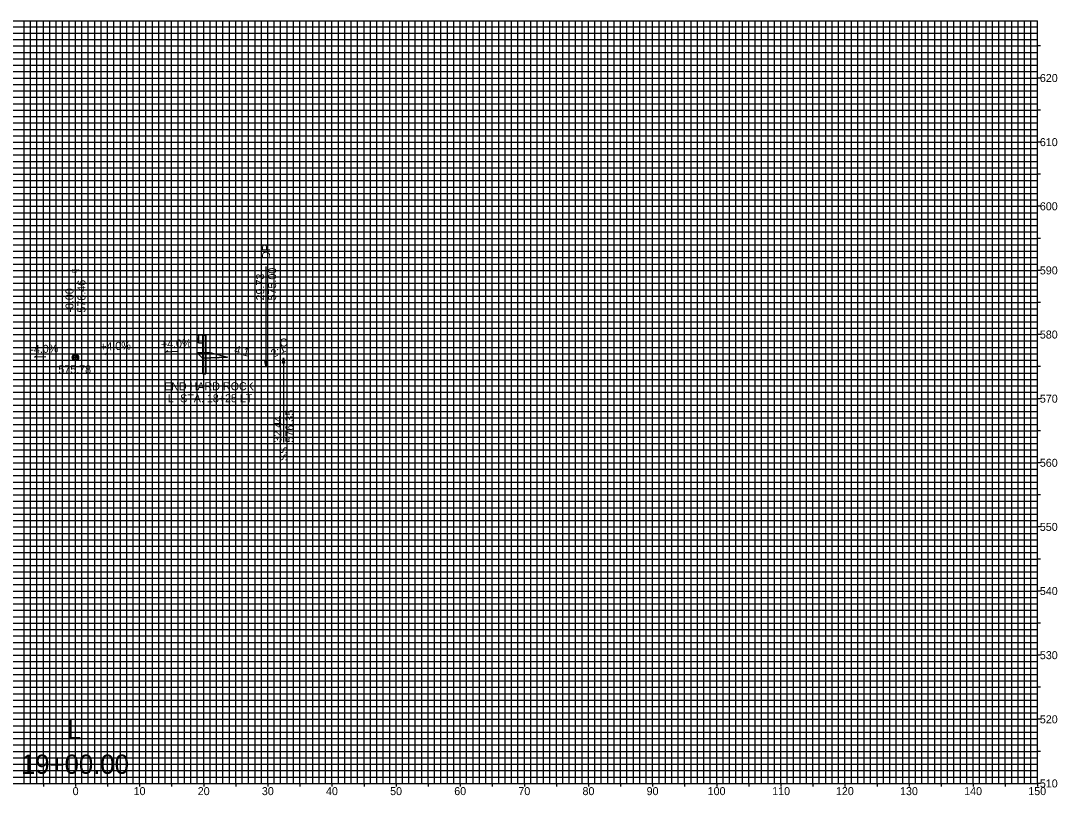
# Model space of a CAD drawing. Extents: x -153 to 153, y 508 to 629.
# Drawn here: x -8.5 to 153.1, y 508.2 to 628.9 of the extents above; entities that cross this region are included whole.
import ezdxf

# ---------------------------------------------------------------- set-up
doc = ezdxf.new("R2010")
doc.units = 0
for name, color, linetype in [('_CIVIL_CONSTRUCTION', 7, 'Continuous'), ('E_NCDOT_XS_Center_Line_Elevation_Label', 7, 'Continuous'), ('Level_63', 7, 'Continuous'), ('P_NCDOT_XS_Label_Grade_Point', 7, 'Continuous'), ('P_NCDOT_XS_Label_Grading_Side_Slope', 7, 'Continuous'), ('P_NCDOT_XS_Label_Slope_Minor', 7, 'Continuous'), ('P_NCDOT_XS_Label_Slope_Superelevation', 7, 'Continuous'), ('P_NCDOT_XS_Leader_Line', 7, 'Continuous'), ('P_NCDOT_XS_Sheet_Alignment_Station_Label', 7, 'Continuous'), ('P_NCDOT_XS_Sheet_Annotation_Label', 7, 'Continuous'), ('P_NCDOT_XS_Sheet_Grid_Border', 7, 'Continuous'), ('Prop XS Grade Point', 7, 'Continuous'), ('Prop XS Label Slope Superelevation', 7, 'Continuous'), ('Scratch_Level_3', 7, 'Continuous'), ('Scratch_Level_4', 7, 'Continuous'), ('Sheet_Grid_Major', 7, 'Continuous'), ('Sheet_Grid_Middle', 7, 'Continuous'), ('Sheet_Grid_Minor', 7, 'Continuous')]:
    doc.layers.add(name, color=color, linetype=linetype)

msp = doc.modelspace()

# ---------------------------------------------------------------- linework, layer by layer
at = {"layer": '_CIVIL_CONSTRUCTION'}
for p, q in [((19.08, 579.79), (18.94, 579.69)), ((18.94, 579.56), (19.15, 579.42)), ((19.15, 579.19), (18.94, 579.05)), ((18.94, 578.92), (19.08, 578.82)), ((19.18, 579.81), (19.09, 579.79)), ((19.09, 578.82), (19.18, 578.8)), ((19.85, 579.89), (19.19, 579.89)), ((19.19, 579.89), (19.19, 578.72)), ((19.19, 579.35), (19.19, 579.3)), ((19.19, 579.3), (19.19, 579.26)), ((19.19, 578.72), (19.85, 578.72)), ((19.85, 579.89), (20.35, 579.89)), ((19.87, 579.89), (19.85, 579.89)), ((19.85, 579.89), (19.85, 573.89)), ((19.87, 573.89), (19.87, 579.89)), ((20.35, 579.89), (20.34, 579.89)), ((20.34, 579.89), (20.34, 573.89)), ((20.35, 573.89), (20.35, 579.89)), ((19.85, 573.89), (20.35, 573.89)), ((19.85, 573.89), (19.87, 573.89)), ((20.34, 573.89), (20.35, 573.89))]:
    msp.add_line(p, q, dxfattribs=at)
for centre, radius, start, end in [((18.99, 579.63), 0.0787, 125.2976, 235.3478), ((18.99, 578.98), 0.0787, 124.6522, 234.7024), ((19.1, 579.76), 0.0328, 100, 125.2976), ((19.1, 578.85), 0.0328, 234.7024, 260), ((19.11, 579.35), 0.0787, 0.02, 55.3478), ((19.11, 579.26), 0.0787, 304.6522, 359.98)]:
    msp.add_arc(centre, radius, start, end, dxfattribs=at)
at = {"layer": 'E_NCDOT_XS_Center_Line_Elevation_Label'}
for p, q in [((4.6, 576.89), (4.93, 577.14)), ((14.06, 577.27), (14.39, 577.52)), ((15.85, 577.34), (14.06, 577.27)), ((-6.4, 576.45), (-6.07, 576.7)), ((-4.6, 576.52), (-6.4, 576.45)), ((6.4, 576.96), (4.6, 576.89))]:
    msp.add_line(p, q, dxfattribs=at)
at = {"layer": 'Level_63'}
msp.add_line((11, 576.9), (11, 577.53), dxfattribs=at)
at = {"layer": 'P_NCDOT_XS_Label_Grade_Point'}
for p, q in [((29.73, 575), (29.73, 590.6)), ((0, 576.46), (0, 588.94)), ((32.44, 576.35), (32.44, 563.15)), ((32.44, 576.35), (32.44, 563.15))]:
    msp.add_line(p, q, dxfattribs=at)
for points in [[(0.3, 576.16), (-0.3, 576.16), (-0.3, 576.76), (0.3, 576.76)], [(29.73, 575), (29.55, 575.82), (29.9, 575.82)], [(32.44, 576.35), (32.62, 575.53), (32.27, 575.53)], [(32.44, 576.35), (32.62, 575.53), (32.27, 575.53)]]:
    msp.add_lwpolyline(points, close=True, dxfattribs=at)
at = {"layer": 'P_NCDOT_XS_Sheet_Grid_Border'}
for p, q in [((-150, 628.94), (150, 628.94)), ((150, 510), (150, 628.94)), ((-150, 510), (150, 510))]:
    msp.add_line(p, q, dxfattribs=at)
at = {"layer": 'Prop XS Label Slope Superelevation'}
for p, q in [((-0.5, 576.46), (0.5, 576.46)), ((0, 576.96), (0, 575.96))]:
    msp.add_line(p, q, dxfattribs=at)
for points in [[(-0.5, 576.46), (0, 576.46), (0, 576.96)], [(0.5, 576.46), (0, 576.46), (0, 575.96)]]:
    msp.add_lwpolyline(points, dxfattribs=at)
msp.add_circle((0, 576.46), 0.5, dxfattribs=at)
for start, end in [(90, 180), (270, 0)]:
    msp.add_arc((0, 576.46), 0.5, start, end, dxfattribs=at)
at = {"layer": 'Scratch_Level_3'}
msp.add_line((19.79, 576.34), (23.73, 576.5), dxfattribs=at)
at = {"layer": 'Scratch_Level_4'}
msp.add_lwpolyline([(18.91, 577.22), (21, 577.18), (23.73, 576.5), (19.79, 576.34)], close=True, dxfattribs=at)
at = {"layer": 'Sheet_Grid_Major'}
for p, q in [((0, 510), (0, 628.94)), ((10, 510), (10, 628.94)), ((20, 510), (20, 628.94)), ((30, 510), (30, 628.94)), ((40, 510), (40, 628.94)), ((50, 510), (50, 628.94)), ((60, 510), (60, 628.94)), ((70, 510), (70, 628.94)), ((80, 510), (80, 628.94)), ((90, 510), (90, 628.94)), ((100, 510), (100, 628.94)), ((110, 510), (110, 628.94)), ((120, 510), (120, 628.94)), ((130, 510), (130, 628.94)), ((140, 510), (140, 628.94)), ((-150, 620), (150, 620)), ((-150, 610), (150, 610)), ((-150, 600), (150, 600)), ((-150, 590), (150, 590)), ((-150, 580), (150, 580)), ((-150, 570), (150, 570)), ((-150, 560), (150, 560)), ((-150, 550), (150, 550)), ((-150, 540), (150, 540)), ((-150, 530), (150, 530)), ((-150, 520), (150, 520))]:
    msp.add_line(p, q, dxfattribs=at)
at = {"layer": 'Sheet_Grid_Middle'}
for p, q in [((-5, 510), (-5, 628.94)), ((0, 510), (0, 628.94)), ((5, 510), (5, 628.94)), ((10, 510), (10, 628.94)), ((15, 510), (15, 628.94)), ((20, 510), (20, 628.94)), ((25, 510), (25, 628.94)), ((30, 510), (30, 628.94)), ((35, 510), (35, 628.94)), ((40, 510), (40, 628.94)), ((45, 510), (45, 628.94)), ((50, 510), (50, 628.94)), ((55, 510), (55, 628.94)), ((60, 510), (60, 628.94)), ((65, 510), (65, 628.94)), ((70, 510), (70, 628.94)), ((75, 510), (75, 628.94)), ((80, 510), (80, 628.94)), ((85, 510), (85, 628.94)), ((90, 510), (90, 628.94)), ((95, 510), (95, 628.94)), ((100, 510), (100, 628.94)), ((105, 510), (105, 628.94)), ((110, 510), (110, 628.94)), ((115, 510), (115, 628.94)), ((120, 510), (120, 628.94)), ((125, 510), (125, 628.94)), ((130, 510), (130, 628.94)), ((135, 510), (135, 628.94)), ((140, 510), (140, 628.94)), ((145, 510), (145, 628.94)), ((-150, 625), (150, 625)), ((150.48, 625), (150, 625)), ((-150, 620), (150, 620)), ((150.48, 620), (150, 620)), ((-150, 615), (150, 615)), ((150.48, 615), (150, 615)), ((-150, 610), (150, 610)), ((150.48, 610), (150, 610)), ((-150, 605), (150, 605)), ((150.48, 605), (150, 605)), ((-150, 600), (150, 600)), ((150.48, 600), (150, 600)), ((-150, 595), (150, 595)), ((150.48, 595), (150, 595)), ((-150, 590), (150, 590)), ((150.48, 590), (150, 590)), ((-150, 585), (150, 585)), ((150.48, 585), (150, 585)), ((-150, 580), (150, 580)), ((150.48, 580), (150, 580)), ((-150, 575), (150, 575)), ((150.48, 575), (150, 575)), ((-150, 570), (150, 570)), ((150.48, 570), (150, 570)), ((-150, 565), (150, 565)), ((150.48, 565), (150, 565)), ((-150, 560), (150, 560)), ((150.48, 560), (150, 560)), ((-150, 555), (150, 555)), ((150.48, 555), (150, 555)), ((-150, 550), (150, 550)), ((150.48, 550), (150, 550)), ((-150, 545), (150, 545)), ((150.48, 545), (150, 545)), ((-150, 540), (150, 540)), ((150.48, 540), (150, 540)), ((-150, 535), (150, 535)), ((150.48, 535), (150, 535)), ((-150, 530), (150, 530)), ((150.48, 530), (150, 530)), ((-150, 525), (150, 525)), ((150.48, 525), (150, 525)), ((-150, 520), (150, 520)), ((150.48, 520), (150, 520)), ((-150, 515), (150, 515)), ((150.48, 515), (150, 515)), ((-5, 510), (-5, 509.52)), ((0, 510), (0, 509.52)), ((5, 510), (5, 509.52)), ((10, 510), (10, 509.52)), ((15, 510), (15, 509.52)), ((20, 510), (20, 509.52)), ((25, 510), (25, 509.52)), ((30, 510), (30, 509.52)), ((35, 510), (35, 509.52)), ((40, 510), (40, 509.52)), ((45, 510), (45, 509.52)), ((50, 510), (50, 509.52)), ((55, 510), (55, 509.52)), ((60, 510), (60, 509.52)), ((65, 510), (65, 509.52)), ((70, 510), (70, 509.52)), ((75, 510), (75, 509.52)), ((80, 510), (80, 509.52)), ((85, 510), (85, 509.52)), ((90, 510), (90, 509.52)), ((95, 510), (95, 509.52)), ((100, 510), (100, 509.52)), ((105, 510), (105, 509.52)), ((110, 510), (110, 509.52)), ((115, 510), (115, 509.52)), ((120, 510), (120, 509.52)), ((125, 510), (125, 509.52)), ((130, 510), (130, 509.52)), ((135, 510), (135, 509.52)), ((140, 510), (140, 509.52)), ((145, 510), (145, 509.52)), ((150, 510), (150, 509.52)), ((150.48, 510), (150, 510))]:
    msp.add_line(p, q, dxfattribs=at)
at = {"layer": 'Sheet_Grid_Minor'}
for p, q in [((-8, 510), (-8, 628.94)), ((-7, 510), (-7, 628.94)), ((-6, 510), (-6, 628.94)), ((-4, 510), (-4, 628.94)), ((-3, 510), (-3, 628.94)), ((-2, 510), (-2, 628.94)), ((-1, 510), (-1, 628.94)), ((1, 510), (1, 628.94)), ((2, 510), (2, 628.94)), ((3, 510), (3, 628.94)), ((4, 510), (4, 628.94)), ((6, 510), (6, 628.94)), ((7, 510), (7, 628.94)), ((8, 510), (8, 628.94)), ((9, 510), (9, 628.94)), ((11, 510), (11, 628.94)), ((12, 510), (12, 628.94)), ((13, 510), (13, 628.94)), ((14, 510), (14, 628.94)), ((16, 510), (16, 628.94)), ((17, 510), (17, 628.94)), ((18, 510), (18, 628.94)), ((19, 510), (19, 628.94)), ((21, 510), (21, 628.94)), ((22, 510), (22, 628.94)), ((23, 510), (23, 628.94)), ((24, 510), (24, 628.94)), ((26, 510), (26, 628.94)), ((27, 510), (27, 628.94)), ((28, 510), (28, 628.94)), ((29, 510), (29, 628.94)), ((31, 510), (31, 628.94)), ((32, 510), (32, 628.94)), ((33, 510), (33, 628.94)), ((34, 510), (34, 628.94)), ((36, 510), (36, 628.94)), ((37, 510), (37, 628.94)), ((38, 510), (38, 628.94)), ((39, 510), (39, 628.94)), ((41, 510), (41, 628.94)), ((42, 510), (42, 628.94)), ((43, 510), (43, 628.94)), ((44, 510), (44, 628.94)), ((46, 510), (46, 628.94)), ((47, 510), (47, 628.94)), ((48, 510), (48, 628.94)), ((49, 510), (49, 628.94)), ((51, 510), (51, 628.94)), ((52, 510), (52, 628.94)), ((53, 510), (53, 628.94)), ((54, 510), (54, 628.94)), ((56, 510), (56, 628.94)), ((57, 510), (57, 628.94)), ((58, 510), (58, 628.94)), ((59, 510), (59, 628.94)), ((61, 510), (61, 628.94)), ((62, 510), (62, 628.94)), ((63, 510), (63, 628.94)), ((64, 510), (64, 628.94)), ((66, 510), (66, 628.94)), ((67, 510), (67, 628.94)), ((68, 510), (68, 628.94)), ((69, 510), (69, 628.94)), ((71, 510), (71, 628.94)), ((72, 510), (72, 628.94)), ((73, 510), (73, 628.94)), ((74, 510), (74, 628.94)), ((76, 510), (76, 628.94)), ((77, 510), (77, 628.94)), ((78, 510), (78, 628.94)), ((79, 510), (79, 628.94)), ((81, 510), (81, 628.94)), ((82, 510), (82, 628.94)), ((83, 510), (83, 628.94)), ((84, 510), (84, 628.94)), ((86, 510), (86, 628.94)), ((87, 510), (87, 628.94)), ((88, 510), (88, 628.94)), ((89, 510), (89, 628.94)), ((91, 510), (91, 628.94)), ((92, 510), (92, 628.94)), ((93, 510), (93, 628.94)), ((94, 510), (94, 628.94)), ((96, 510), (96, 628.94)), ((97, 510), (97, 628.94)), ((98, 510), (98, 628.94)), ((99, 510), (99, 628.94)), ((101, 510), (101, 628.94)), ((102, 510), (102, 628.94)), ((103, 510), (103, 628.94)), ((104, 510), (104, 628.94)), ((106, 510), (106, 628.94)), ((107, 510), (107, 628.94)), ((108, 510), (108, 628.94)), ((109, 510), (109, 628.94)), ((111, 510), (111, 628.94)), ((112, 510), (112, 628.94)), ((113, 510), (113, 628.94)), ((114, 510), (114, 628.94)), ((116, 510), (116, 628.94)), ((117, 510), (117, 628.94)), ((118, 510), (118, 628.94)), ((119, 510), (119, 628.94)), ((121, 510), (121, 628.94)), ((122, 510), (122, 628.94)), ((123, 510), (123, 628.94)), ((124, 510), (124, 628.94)), ((126, 510), (126, 628.94)), ((127, 510), (127, 628.94)), ((128, 510), (128, 628.94)), ((129, 510), (129, 628.94)), ((131, 510), (131, 628.94)), ((132, 510), (132, 628.94)), ((133, 510), (133, 628.94)), ((134, 510), (134, 628.94)), ((136, 510), (136, 628.94)), ((137, 510), (137, 628.94)), ((138, 510), (138, 628.94)), ((139, 510), (139, 628.94)), ((141, 510), (141, 628.94)), ((142, 510), (142, 628.94)), ((143, 510), (143, 628.94)), ((144, 510), (144, 628.94)), ((146, 510), (146, 628.94)), ((147, 510), (147, 628.94)), ((148, 510), (148, 628.94)), ((149, 510), (149, 628.94)), ((-150, 628), (150, 628)), ((-150, 627), (150, 627)), ((-150, 626), (150, 626)), ((-150, 624), (150, 624)), ((-150, 623), (150, 623)), ((-150, 622), (150, 622)), ((-150, 621), (150, 621)), ((-150, 619), (150, 619)), ((-150, 618), (150, 618)), ((-150, 617), (150, 617)), ((-150, 616), (150, 616)), ((-150, 614), (150, 614)), ((-150, 613), (150, 613)), ((-150, 612), (150, 612)), ((-150, 611), (150, 611)), ((-150, 609), (150, 609)), ((-150, 608), (150, 608)), ((-150, 607), (150, 607)), ((-150, 606), (150, 606)), ((-150, 604), (150, 604)), ((-150, 603), (150, 603)), ((-150, 602), (150, 602)), ((-150, 601), (150, 601)), ((-150, 599), (150, 599)), ((-150, 598), (150, 598)), ((-150, 597), (150, 597)), ((-150, 596), (150, 596)), ((-150, 594), (150, 594)), ((-150, 593), (150, 593)), ((-150, 592), (150, 592)), ((-150, 591), (150, 591)), ((-150, 589), (150, 589)), ((-150, 588), (150, 588)), ((-150, 587), (150, 587)), ((-150, 586), (150, 586)), ((-150, 584), (150, 584)), ((-150, 583), (150, 583)), ((-150, 582), (150, 582)), ((-150, 581), (150, 581)), ((-150, 579), (150, 579)), ((-150, 578), (150, 578)), ((-150, 577), (150, 577)), ((-150, 576), (150, 576)), ((-150, 574), (150, 574)), ((-150, 573), (150, 573)), ((-150, 572), (150, 572)), ((-150, 571), (150, 571)), ((-150, 569), (150, 569)), ((-150, 568), (150, 568)), ((-150, 567), (150, 567)), ((-150, 566), (150, 566)), ((-150, 564), (150, 564)), ((-150, 563), (150, 563)), ((-150, 562), (150, 562)), ((-150, 561), (150, 561)), ((-150, 559), (150, 559)), ((-150, 558), (150, 558)), ((-150, 557), (150, 557)), ((-150, 556), (150, 556)), ((-150, 554), (150, 554)), ((-150, 553), (150, 553)), ((-150, 552), (150, 552)), ((-150, 551), (150, 551)), ((-150, 549), (150, 549)), ((-150, 548), (150, 548)), ((-150, 547), (150, 547)), ((-150, 546), (150, 546)), ((-150, 544), (150, 544)), ((-150, 543), (150, 543)), ((-150, 542), (150, 542)), ((-150, 541), (150, 541)), ((-150, 539), (150, 539)), ((-150, 538), (150, 538)), ((-150, 537), (150, 537)), ((-150, 536), (150, 536)), ((-150, 534), (150, 534)), ((-150, 533), (150, 533)), ((-150, 532), (150, 532)), ((-150, 531), (150, 531)), ((-150, 529), (150, 529)), ((-150, 528), (150, 528)), ((-150, 527), (150, 527)), ((-150, 526), (150, 526)), ((-150, 524), (150, 524)), ((-150, 523), (150, 523)), ((-150, 522), (150, 522)), ((-150, 521), (150, 521)), ((-150, 519), (150, 519)), ((-150, 518), (150, 518)), ((-150, 517), (150, 517)), ((-150, 516), (150, 516)), ((-150, 514), (150, 514)), ((-150, 513), (150, 513)), ((-150, 512), (150, 512)), ((-150, 511), (150, 511))]:
    msp.add_line(p, q, dxfattribs=at)

# ---------------------------------------------------------------- texts
at = {"layer": 'P_NCDOT_XS_Label_Grading_Side_Slope'}
msp.add_text('GP', height=0.624, dxfattribs=at).set_placement((-0.61, 589.61))
for s, p in [('576.46', (1.56, 583.42)), ('-0.00', (-0.31, 583.42))]:
    msp.add_text(s, height=1.248, rotation=90, dxfattribs=at).set_placement(p)
at = {"layer": 'P_NCDOT_XS_Label_Slope_Minor'}
msp.add_text('575.78', height=1.248, dxfattribs=at).set_placement((-2.67, 573.95))
at = {"layer": 'P_NCDOT_XS_Label_Slope_Superelevation'}
for s, rotation, p in [('+4.0%', 2.2906, (13.34, 577.87)), ('4:1', 345.9638, (24.67, 577.12)), ('2:1', 26.5651, (30.86, 576.36))]:
    msp.add_text(s, height=1.248, rotation=rotation, dxfattribs=at).set_placement(p)
at = {"layer": 'P_NCDOT_XS_Leader_Line'}
for s, p in [('+4.0%', (3.88, 577.49)), ('-4.0%', (-7.03, 577.06))]:
    msp.add_text(s, height=1.248, rotation=2.2906, dxfattribs=at).set_placement(p)
at = {"layer": 'P_NCDOT_XS_Sheet_Alignment_Station_Label'}
for s, p in [('L', (-1.32, 516.9)), ('19+00.00', (-8.5, 511.5))]:
    msp.add_text(s, height=3, dxfattribs=at).set_placement(p)
at = {"layer": 'P_NCDOT_XS_Sheet_Annotation_Label'}
for s, height, p in [('620', 1.248, (150.39, 619.38)), ('610', 1.248, (150.39, 609.38)), ('600', 1.248, (150.39, 599.38)), ('590', 1.248, (150.39, 589.38)), ('580', 1.248, (150.39, 579.38)), ('570', 1.248, (150.39, 569.38)), ('560', 1.248, (150.39, 559.38)), ('550', 1.248, (150.39, 549.38)), ('540', 1.248, (150.39, 539.38)), ('530', 1.248, (150.39, 529.38)), ('520', 1.248, (150.39, 519.38)), ('0', 1.25, (-0.44, 508.18)), ('10', 1.248, (9.07, 508.18)), ('20', 1.248, (19.07, 508.18)), ('30', 1.248, (29.07, 508.18)), ('40', 1.248, (39.07, 508.18)), ('50', 1.248, (49.07, 508.18)), ('60', 1.248, (59.07, 508.18)), ('70', 1.248, (69.07, 508.18)), ('80', 1.248, (79.07, 508.18)), ('90', 1.248, (89.07, 508.18)), ('100', 1.248, (98.59, 508.18)), ('110', 1.248, (108.65, 508.18)), ('120', 1.248, (118.59, 508.18)), ('130', 1.248, (128.59, 508.18)), ('140', 1.248, (138.59, 508.18)), ('150', 1.248, (148.59, 508.18)), ('510', 1.248, (150.39, 509.38))]:
    msp.add_text(s, height=height, dxfattribs=at).set_placement(p)
at = {"layer": 'Prop XS Grade Point'}
for s, rotation, p in [('DP', 90, (30.35, 591.8)), ('575.00', 90, (31.29, 585.32)), ('29.73', 90, (29.42, 585.32)), ('END HARD ROCK', 0.076, (13.82, 571.3)), ('-L- STA. 18+25 LT', 0.076, (13.82, 569.43)), ('576.35', 90, (34, 563.15)), ('576.35', 90, (34, 563.15)), ('32.44', 90, (32.13, 563.15)), ('32.44', 90, (32.13, 563.15)), ('SS', 90, (33.07, 560.27)), ('SS', 90, (33.07, 560.27))]:
    msp.add_text(s, height=1.248, rotation=rotation, dxfattribs=at).set_placement(p)
msp.add_text('C', height=1.25, dxfattribs=at).set_placement((31.84, 578.13))
msp.add_text('C', height=1.25, dxfattribs=at).set_placement((31.84, 578.13))

doc.saveas('drawing.dxf')
